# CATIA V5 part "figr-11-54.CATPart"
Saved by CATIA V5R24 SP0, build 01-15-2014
Part number: Part1
Bounding box of the stored display mesh (mm): x -49.998 to 49.998, y -70 to 70, z 0 to 80.773
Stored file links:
  D:\KAVITA\CATIA V5-6R2014 Project_ Kavita\CATIA V5-6R2014_partfiles\Partfiles\c11_catia_v5-6r2014_prt\figr-11-54.CATPart
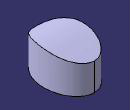
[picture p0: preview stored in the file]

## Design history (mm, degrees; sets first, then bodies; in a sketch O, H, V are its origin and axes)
Set1
  Extrude1: Element1 Sketch2, Lim1 82, Lim2 70, Direction yz-plane
Body1 (main body)
  Sketch1 on xy-plane, origin (0, 0, 0), H (1, 0, 0), V (0, 1, 0)
    ellipse A1 centre (0, 0) semi-axes 70, 50 rotation 90
    point P1 (50, 0)
    coincidence: P1 H, A1 P1
  Pad1: profile Sketch1, direction (0, 0, 1), length 84
  Split1: SplitPlane Extrude1
  Sketch2 on yz-plane, origin (0, 0, 0), H (0, 1, 0), V (0, 0, 1)
    spline S1 through (-90, 50) (-30, 80) (50, 70) (90, 60)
